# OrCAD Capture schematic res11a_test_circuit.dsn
size Custom; title: RES11A  Matched, Thin-Film Resistor Dividers with 1-KOhm Inputs; rev: 1.1; note: SLPS785 - DEC '23 - REV OCT '25
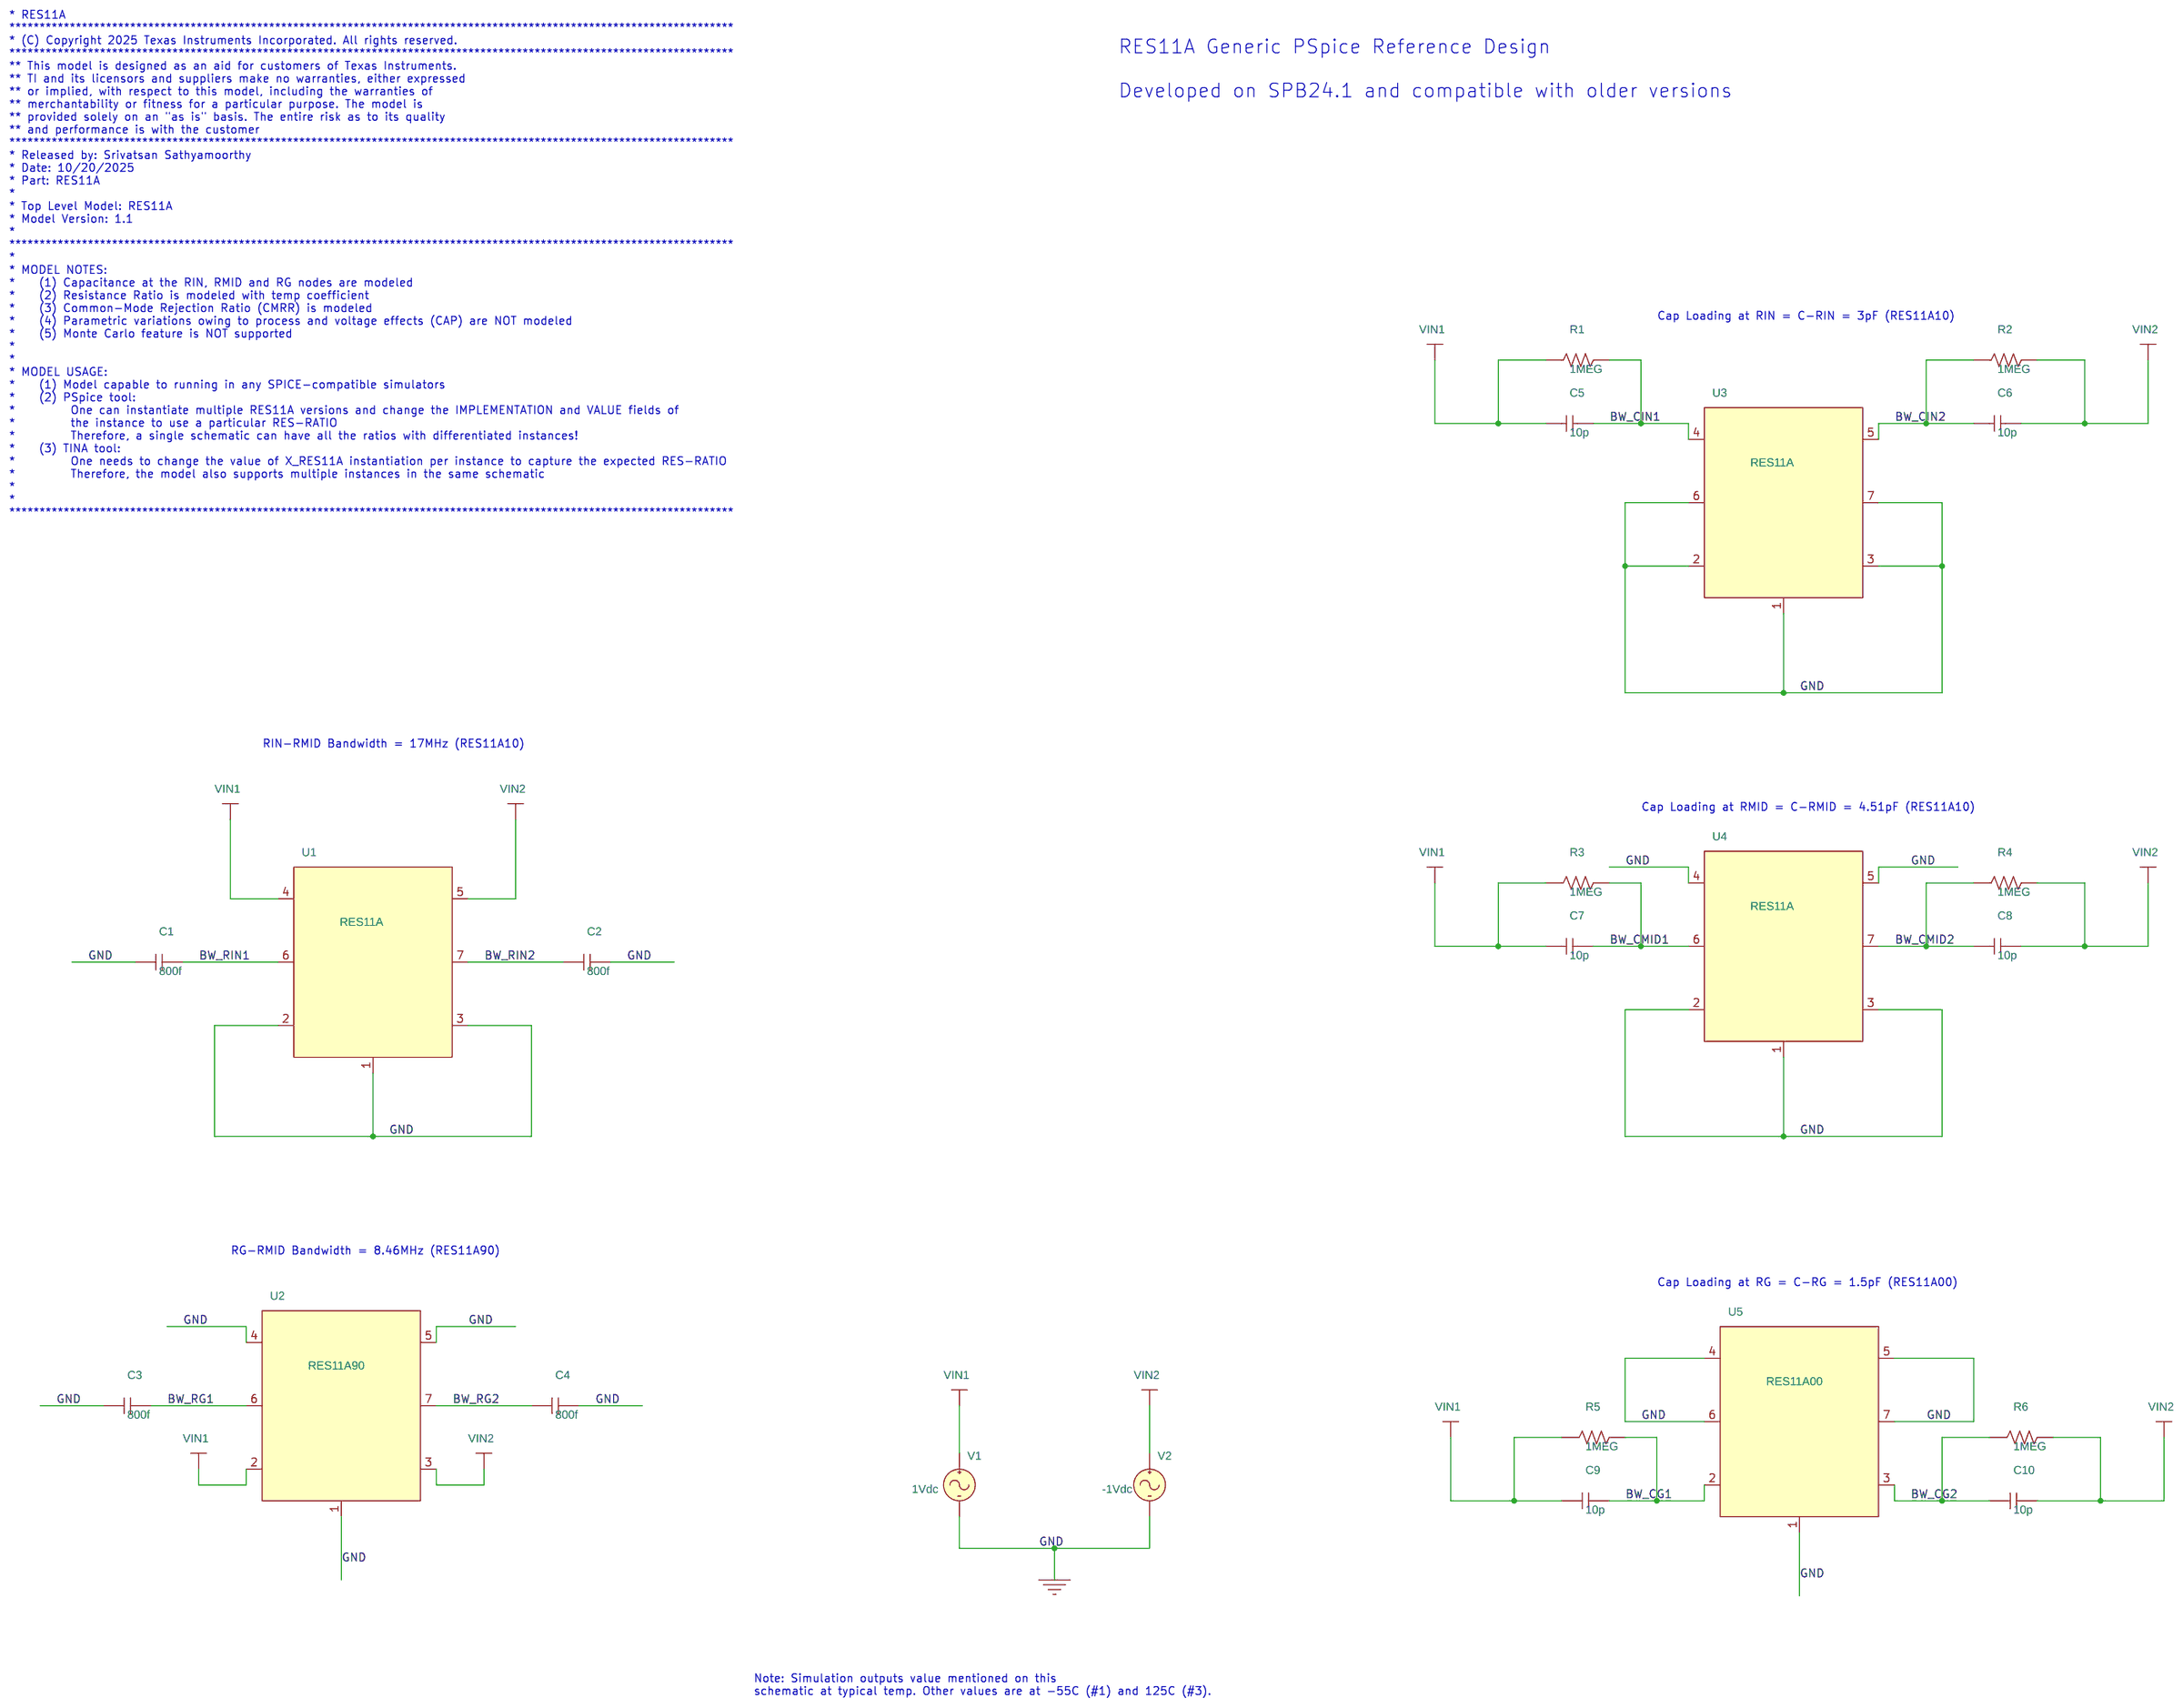
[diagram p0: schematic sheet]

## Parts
C1  800f  [cap196]
C2  800f  [cap196]
C3  800f  [cap196]
C4  800f  [cap196]
C5  10p  [cap196]
C6  10p  [cap196]
C7  10p  [cap196]
C8  10p  [cap196]
C9  10p  [cap196]
C10  10p  [cap196]
R1  1MEG  [AXRC05]
R2  1MEG  [AXRC05]
R3  1MEG  [AXRC05]
R4  1MEG  [AXRC05]
R5  1MEG  [AXRC05]
R6  1MEG  [AXRC05]
U1  RES11A
U2  RES11A90
U3  RES11A
U4  RES11A
U5  RES11A00
V1  VAC
V2  VAC

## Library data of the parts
C1-C10 = C
R1-R6 = R
U1-U4 = RES11A
U5 = RES11A00
V1 = VAC: DC: 1Vdc
V2 = VAC: DC: -1Vdc

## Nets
VIN1: C5.1 C7.1 C9.1 R1.1 R3.1 R5.1 U1.4(RIN1) U2.2(RG1) V1.1(+)
VIN2: C6.2 C8.2 C10.2 R2.2 R4.2 R6.2 U1.5(RIN2) U2.3(RG2) V2.1(+)
0: C1.1 C2.2 C3.1 C4.2 U1.1(GND) U1.2(RG1) U1.3(RG2) U2.1(GND) U2.4(RIN1) U2.5(RIN2) U3.1(GND) U3.2(RG1) U3.3(RG2) U3.6(RMID1) U3.7(RMID2) U4.1(GND) U4.2(RG1) U4.3(RG2) U4.4(RIN1) U4.5(RIN2) U5.1(GND) U5.4(RIN1) U5.5(RIN2) U5.6(RMID1) U5.7(RMID2) V1.2(-) V2.2(-)
BW_CG1: C9.2 R5.2 U5.2(RG1)
BW_CG2: C10.1 R6.1 U5.3(RG2)
BW_CIN1: C5.2 R1.2 U3.4(RIN1)
BW_CIN2: C6.1 R2.1 U3.5(RIN2)
BW_CMID1: C7.2 R3.2 U4.6(RMID1)
BW_CMID2: C8.1 R4.1 U4.7(RMID2)
BW_RG1: C3.2 U2.6(RMID1)
BW_RG2: C4.1 U2.7(RMID2)
BW_RIN1: C1.2 U1.6(RMID1)
BW_RIN2: C2.1 U1.7(RMID2)

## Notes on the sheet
- * RES11A
  ************************************************************************************************************************
  * (C) Copyright 2025 Texas Instruments Incorporated. All rights reserved.
  ************************************************************************************************************************
  ** This model is designed as an aid for customers of Texas Instruments.
  ** TI and its licensors and suppliers make no warranties, either expressed
  ** or implied, with respect to this model, including the warranties of
  ** merchantability or fitness for a particular purpose. The model is
  ** provided solely on an "as is" basis. The entire risk as to its quality
  ** and performance is with the customer
  ************************************************************************************************************************
  * Released by: Srivatsan Sathyamoorthy
  * Date: 10/20/2025
  * Part: RES11A
  *
  * Top Level Model: RES11A
  * Model Version: 1.1
  *
  ************************************************************************************************************************
  *
  * MODEL NOTES:
  *	(1) Capacitance at the RIN, RMID and RG nodes are modeled
  *	(2) Resistance Ratio is modeled with temp coefficient
  *	(3) Common-Mode Rejection Ratio (CMRR) is modeled
  *	(4) Parametric variations owing to process and voltage effects (CAP) are NOT modeled
  *	(5) Monte Carlo feature is NOT supported
  *
  *
  * MODEL USAGE:
  *	(1) Model capable to running in any SPICE-compatible simulators
  *	(2) PSpice tool:
  *		One can instantiate multiple RES11A versions and change the IMPLEMENTATION and VALUE fields of
  *		the instance to use a particular RES-RATIO
  *		Therefore, a single schematic can have all the ratios with differentiated instances!
  *	(3) TINA tool:
  *		One needs to change the value of X_RES11A instantiation per instance to capture the expected RES-RATIO
  *		Therefore, the model also supports multiple instances in the same schematic
  *
  *
  ************************************************************************************************************************
- RES11A Generic PSpice Reference Design
  Developed on SPB24.1 and compatible with older versions
- Cap Loading at RIN = C-RIN = 3pF (RES11A10)
- RIN-RMID Bandwidth = 17MHz (RES11A10)
- Cap Loading at RMID = C-RMID = 4.51pF (RES11A10)
- RG-RMID Bandwidth = 8.46MHz (RES11A90)
- Cap Loading at RG = C-RG = 1.5pF (RES11A00)
- Note: Simulation outputs value mentioned on this
  schematic at typical temp. Other values are at -55C (#1) and 125C (#3).
